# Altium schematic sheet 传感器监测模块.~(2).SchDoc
size A4
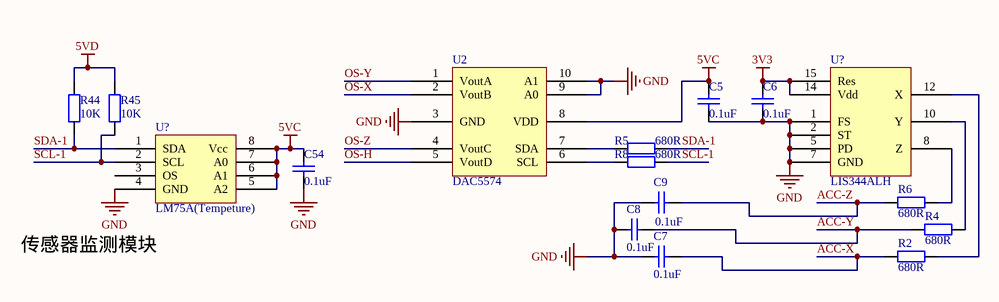
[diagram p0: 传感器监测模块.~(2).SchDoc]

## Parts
(Parts that share a designator on the sheet are numbered #1, #2 ... from top to bottom, then left to right.)
C5  value 0.1uF  [RAD-0.3]  (hidden comment: Cap)
C6  value 0.1uF  [RAD-0.3]  (hidden comment: Cap)
C7  value 0.1uF  [RAD-0.3]  (hidden comment: Cap)
C8  value 0.1uF  [RAD-0.3]  (hidden comment: Cap)
C9  value 0.1uF  [RAD-0.3]  (hidden comment: Cap)
C54  value 0.1uF  [RAD-0.3]  (hidden comment: Cap)
R2  680R  [R0603]
R4  680R  [R0603]
R5  680R  [R0603]
R6  680R  [R0603]
R8  680R  [R0603]
R44  10K  [1608[0603]]
R45  10K  [1608[0603]]
U2  DAC5574
U?#1  LIS344ALH  [LIS344ALH(Acc)]
U?#2  LM75A(Tempeture)  [LM75A]

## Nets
3V3: C6.2 U?#1.14(Vdd) U?#1.15(Res)
5VC: C5.2 C54.2 U2.8(VDD) U?#2.5(A2) U?#2.6(A1) U?#2.7(A0) U?#2.8(Vcc)
5VD: R44.2 R45.2
GND: C5.1 C6.1 C7.2 C8.2 C9.2 C54.1 U2.3(GND) U2.9(A0) U2.10(A1) U?#1.1(FS) U?#1.2(ST) U?#1.5(PD) U?#1.7(GND) U?#2.4(GND)
ACC-X: C7.1 R2.2
ACC-Y: C8.1 R4.2
ACC-Z: C9.1 R6.2
OS-H: U2.5(VoutD)
OS-X: U2.2(VoutB)
OS-Y: U2.1(VoutA)
OS-Z: U2.4(VoutC)
SCL-1: R8.2 R45.1 U?#2.2(SCL)
SDA-1: R5.2 R44.1 U?#2.1(SDA)
NetR2_1: R2.1 U?#1.12(X)
NetR4_1: R4.1 U?#1.10(Y)
NetR5_1: R5.1 U2.7(SDA)
NetR6_1: R6.1 U?#1.8(Z)
NetR8_1: R8.1 U2.6(SCL)

Not connected (* = marked no-connect by the designer): U?#2 3(OS)

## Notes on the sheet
- Labels drawn without touching a wire or pin: 传感器监测模块

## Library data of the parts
C5-C9 C54 = Cap: Capacitor
R2 R4-R6 R8 = R0603
R44 R45 = R0805
U?#1 = ACC(LIS344ALH)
